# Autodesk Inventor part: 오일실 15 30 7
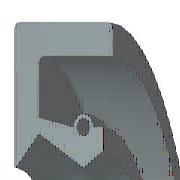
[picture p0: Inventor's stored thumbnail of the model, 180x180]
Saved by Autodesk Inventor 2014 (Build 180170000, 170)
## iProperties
IsCustomPart: 1
Created: 2012-02
Part Number: 오일실 15 30 7
Material: 고무
Description: 오일-실
Document SubType Name: Modeling
Standard: KS B 2804
Designer: mduedu
Standards Organization: KS
Language: ko-KR
Size Designation: D - 15 30 7
Categories: <MemberInstance><Categories><Category DisplayName="샤프트 부품" InternalName="7f7aeb1f-a693-4053-b835-cee3144e0d98" Mnemonic="SHFT"><Category DisplayName="실링" Intern
Density: 0.93 g/cm^3
Appearance: Rubber - Black - Version 1.1
Author: mduedu
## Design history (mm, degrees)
revolve "본체" stored, may be unused: angle "d17" = 90 deg
revolve "스프링1" stored, may be unused: angle "d18" = 90 deg
body "Solid1"
sketch "스케치1"
  geometry: L1 (0, 15)-(7, 15); L2 (7, 13.25)-(1.75, 13.25); L3 (1.75, 9.25)-(4.9, 7.5); L4 (4.9, 7.5)-(0, 7.5); L5 (0, 0)-(9.586, 0) reference; L6 (4.9, 7.5)-(6.3, 8.375); L7 (0, 18)-(0, -3) reference; L8 (-1.941, 0)-(11.507, 0) reference; L9 (4.2, 9.6)-(1.75, 10.09); L10 (1.75, 10.09)-(1.75, 13.25); L11 (0, 15)-(0, 7.588); L12 (4.9, 7.5)-(0, 7.5); L13 (1.75, 9.25)-(0.152, 7.528); L14 (7, 15)-(7, 13.25); L15 (5.6, 9.6)-(6.3, 9.6); L16 (6.3, 9.6)-(6.3, 8.375); C1 r 0.455 at (4.9, 9.6); A1 r 0.7 centre (4.9, 9.6) between (5.6, 9.6) and (4.2, 9.6); A2 r 0.088 centre (0.088, 7.588) between (0, 7.588) and (0.152, 7.528); 1 further point
  constraints: 28 end point, 5 horizontal alignment, 5 point on line, 4 point on circle, 4 vertical alignment, 3 centre point, 3 tangent, 2 collinear, 2 horizontal, 2 perpendicular, 1 coincident, 1 parallel
  dimensions: "d0" = 30 diameter of L1 L5 (= SD2); "d1" = 1.75 distance of L1.end L2.start (= SD); "d2" = 0.91 diameter of C1 (= SPDI); "d3" = 1.4 diameter of A1 (= SPDA); "d4" = 15 diameter of L3.end L5 (= NND); "d5" = 18.5 diameter of L3.start L5 (= TKDM); "d7" = 20.18 diameter of L9.end L5 (= TKDM + 0.24 x SWDT); "d8" = 1.75 distance between parallel lines of L11 L10 (= SD); "d9" = 4.9 distance from line of L11 C1.centre (= SPDST); "d10" = 19.2 diameter of C1.centre L5 (= HLDM); "d11" = 0.0875 radius of A2 (= 0.25 x LAB); "d12" = 6.3 distance between parallel lines of L11 L16 (= SDI); "d13" = 16.75 diameter of L6.end L5 (= ABDM); "d14" = 7 distance from line of L11 L1.end (= SWDT)
fillet "모깎기1" dims "d6" = 0.3 (= RR)
other parameters: "SD2" = 30 [user parameter; used in 1 equation term], "SWDT" = 7 [user parameter; used in 2 equation terms], "RR" = 0.3 [user parameter; used in 1 equation term], "SD" = 1.75 [user parameter; used in 2 equation terms], "NND" = 15 [user parameter; used in 1 equation term], "SPDA" = 1.4 [user parameter; used in 1 equation term], "SPDI" = 0.91 [user parameter; used in 1 equation term], "TKDM" = 18.5 [user parameter; used in 2 equation terms], "HLDM" = 19.2 [user parameter; used in 1 equation term], "ABDM" = 16.75 [user parameter; used in 1 equation term], "SDI" = 6.3 [user parameter; used in 1 equation term], "SPDST" = 4.9 [user parameter; used in 1 equation term], "LAB" = 0.35 [user parameter; used in 1 equation term], "d15" = 0, "d16" = 0, "d19" = 0
